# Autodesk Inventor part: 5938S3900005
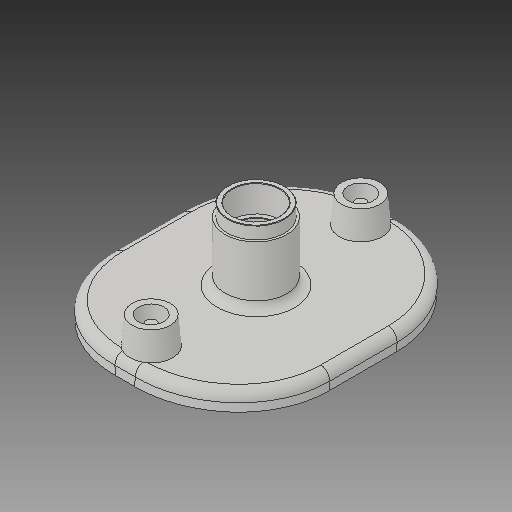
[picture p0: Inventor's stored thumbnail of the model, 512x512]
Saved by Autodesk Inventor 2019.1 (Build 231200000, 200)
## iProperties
Created: 2017-08
Part Number: 5938S3900005
Material: Generic
Description: PLASSON SENSOR ADAPTOR WITH STAINLESS STEEL THREAD 18''48''IPSx1/2''
Document SubType Name: Modeling
Designer: Кирилл
Density: 1 g/cm^3
Appearance: Default
Author: Кирилл
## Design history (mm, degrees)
derived "5938S.ipt"
feature "Solid1::5938S.ipt"
feature "Solid2::5938S.ipt"
feature "Solid3::5938S.ipt"
tag "TaggingFeature1"
body "Solid1"
other parameters: "d0" = 1213.7, "d1" = 84.836, "d3" = 102.87, "d4" = 0, "d5" = 38.1762, "d11" = 788.905, "d38" = 3.6411, "d40" = 624.376, "d41" = 15, "d42" = 41.148, "d46" = 5 deg, "d47" = 4, "d51" = 14, "d52" = 0, "d53" = 3, "d54" = 0, "d75" = 0, "d77" = 0, "d78" = 0.18631, "d82" = 35.052, "d83" = 24.2203, "d84" = 22.3572, "d85" = 14.9048, "d86" = 18.631, "d89" = 10.5156, "d90" = 4.90728, "d95" = 3.175, "d97" = 360 deg, "d99" = 7.0104, "d_" = 1213.7, "B_" = 84.836, "H_" = 35.052, "L_" = 102.87, "G_" = 18.631
